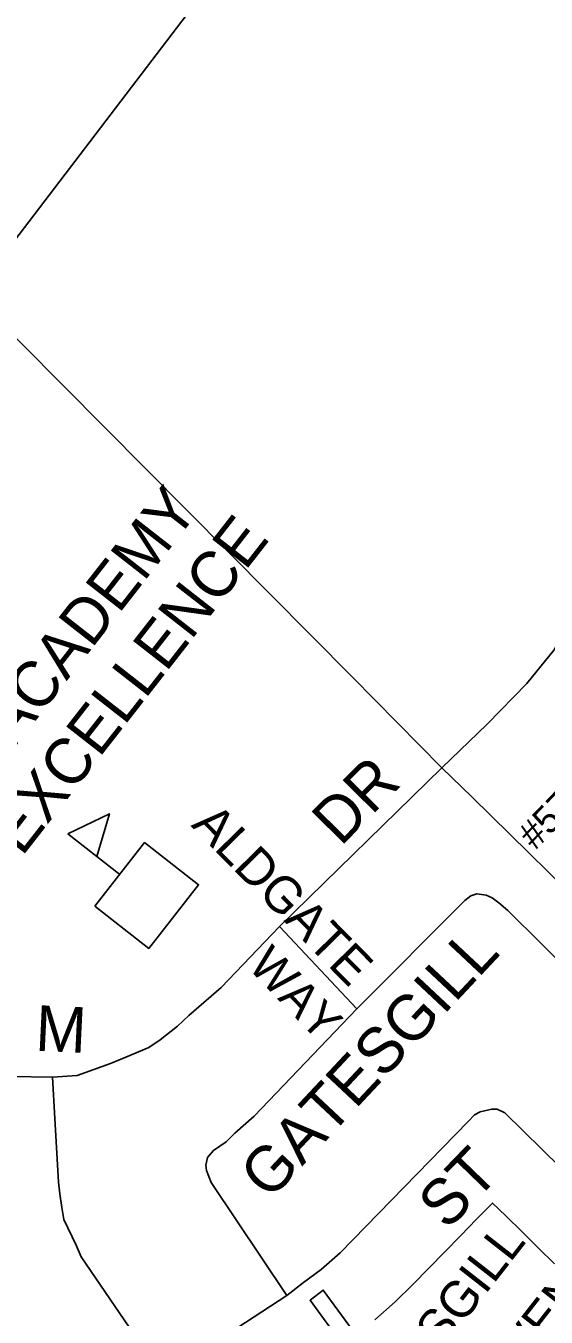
# Model space of a CAD drawing. Extents: x 586326 to 623965, y 4819854 to 4857850.
# Drawn here: x 597777 to 598062, y 4839351 to 4840059 of the extents above; entities that cross this region are included whole.
import ezdxf

# ---------------------------------------------------------------- set-up
doc = ezdxf.new("R2010")
doc.units = 0
for name, color, linetype in [('Cemeteries', 7, 'Continuous'), ('Major Rds and Hwys', 7, 'Continuous'), ('Minor Rd Lbls', 7, 'Continuous'), ('Minor Rds', 7, 'Continuous'), ('Park Lbls', 7, 'Continuous'), ('Park Outlines', 7, 'Continuous'), ('Private Rd Lbls', 7, 'Continuous'), ('Proposed Secondary Rds', 7, 'Continuous'), ('School Syms_Lbls', 7, 'Continuous'), ('Secondary Rds Lbls', 7, 'Continuous')]:
    doc.layers.add(name, color=color, linetype=linetype)

msp = doc.modelspace()

# ---------------------------------------------------------------- linework, layer by layer
at = {"layer": 'Major Rds and Hwys'}
for points in [[(597747.55, 4839911.46), (597898.45, 4840109.35), (597999.82, 4840250.81)], [(598004.81, 4839652.2), (597955.66, 4839701.74), (597751.53, 4839907.45), (597747.55, 4839911.46)], [(598294.8, 4839367.57), (598241.06, 4839420.31), (598021.17, 4839636.15), (598004.81, 4839652.2)]]:
    msp.add_lwpolyline(points, dxfattribs=at)
at = {"layer": 'Minor Rds'}
for points in [[(598077.81, 4839537.46), (598040.92, 4839573.89), (598035.95, 4839578.09), (598032.36, 4839580.81), (598029.11, 4839582.32), (598023.91, 4839582.98), (598020.64, 4839582.04), (598017.31, 4839579.41), (597958.19, 4839519.93)], [(597915.67, 4839565.21), (597958.19, 4839519.93)], [(597958.19, 4839519.93), (597901.89, 4839461.27), (597891.26, 4839451.82), (597886.54, 4839447.1), (597879.45, 4839442.37), (597876.18, 4839438.56), (597875.41, 4839434.33), (597875.68, 4839431.42), (597878.17, 4839424.87), (597919.78, 4839362.93)], [(597851.74, 4839318.45), (597806.99, 4839384.12), (597804.3, 4839390.42), (597797.5, 4839404.46), (597796.33, 4839411.08), (597795.19, 4839418.56), (597794.53, 4839425.02), (597792.61, 4839459.92), (597791.26, 4839482.53)], [(597919.78, 4839362.93), (597928.95, 4839369.98), (597938.56, 4839377.08), (597948.94, 4839386.32), (598019.13, 4839458.3), (598022.61, 4839461.93), (598025.75, 4839463.52), (598032.06, 4839465.09), (598035.1, 4839464.93), (598039.31, 4839463), (598069.83, 4839433.04)], [(597851.74, 4839318.45), (597919.78, 4839362.93)]]:
    msp.add_lwpolyline(points, dxfattribs=at)
at = {"layer": 'Park Outlines'}
for points in [[(598066.55, 4839380.23), (598057.63, 4839388.98), (598048.71, 4839397.73), (598039.79, 4839406.48), (598032.57, 4839413.55), (598023.82, 4839404.63), (598015.07, 4839395.72), (598006.31, 4839386.8), (597997.56, 4839377.88), (597988.81, 4839368.96), (597979.09, 4839359.45), (597967.93, 4839349.54)], [(597957.7, 4839341.17), (597939.7, 4839365.8), (597932.45, 4839360.28), (597950.64, 4839335.39)]]:
    msp.add_lwpolyline(points, dxfattribs=at)
at = {"layer": 'Proposed Secondary Rds'}
for points in [[(598004.81, 4839652.2), (598029.54, 4839676.08), (598051.33, 4839698.29), (598066.41, 4839716.73), (598071.44, 4839726.37), (598076.89, 4839736.84), (598080.66, 4839748.57), (598083.17, 4839757.79), (598089.88, 4839790.06)], [(598004.81, 4839652.2), (597915.67, 4839565.21)], [(597915.67, 4839565.21), (597883.78, 4839531.74), (597866.06, 4839516.39), (597859.77, 4839510.48), (597850.33, 4839502.94), (597844.01, 4839498.91), (597831.54, 4839493.5), (597823.07, 4839489.97), (597804.71, 4839483.53), (597791.26, 4839482.53)], [(597791.26, 4839482.53), (597768.03, 4839482.92), (597751.11, 4839485.29), (597736.14, 4839488.44), (597712.92, 4839499.07)]]:
    msp.add_lwpolyline(points, dxfattribs=at)
at = {"layer": 'School Syms_Lbls'}
msp.add_line((597828.09, 4839593.74), (597799.68, 4839615.93), dxfattribs=at)
for points in [[(597799.68, 4839615.93), (597822.45, 4839626.96), (597815.54, 4839603.46)], [(597814.45, 4839576.29), (597841.72, 4839611.18), (597871.33, 4839588.05), (597844.06, 4839553.16)]]:
    msp.add_lwpolyline(points, close=True, dxfattribs=at)

# ---------------------------------------------------------------- texts
at = {"layer": 'Cemeteries'}
for s, p in [('(PEEL CO. MANOR)', (598046.65, 4839274.35)), ('EVENTIDE', (598040.71, 4839309.08))]:
    msp.add_text(s, height=20, rotation=52.00002, dxfattribs=at).set_placement(p)
at = {"layer": 'Minor Rd Lbls'}
for s, height, rotation, p in [('ALDGATE', 19.998, 314.43557, (597866.82, 4839620.35)), ('GATESGILL', 25.002, 46.87693, (597910.3, 4839414.51)), ('WAY', 18.998, 313.6678, (597897.74, 4839542.97)), ('ST', 25.002, 45.97104, (598007.64, 4839398.1))]:
    msp.add_text(s, height=height, rotation=rotation, dxfattribs=at).set_placement(p)
at = {"layer": 'Park Lbls'}
msp.add_text('GATESGILL', height=19.992, rotation=52.00002, dxfattribs=at).set_placement((597959.85, 4839275.18))
at = {"layer": 'Private Rd Lbls'}
msp.add_text('#57 BRICKYARD ', height=15, rotation=45.79285, dxfattribs=at).set_placement((598055.94, 4839606.62))
at = {"layer": 'School Syms_Lbls'}
for s, p in [('XYNA ACADEMY', (597708.57, 4839583.87)), ('OF EXCELLENCE', (597740.19, 4839559.16))]:
    msp.add_text(s, height=25, rotation=52.00002, dxfattribs=at).set_placement(p)
at = {"layer": 'Secondary Rds Lbls'}
for s, height, rotation, p in [('DR', 25.002, 45.35152, (597949.24, 4839608.63)), ('M', 25, 357.27371, (597781.48, 4839497.1))]:
    msp.add_text(s, height=height, rotation=rotation, dxfattribs=at).set_placement(p)

doc.saveas('drawing.dxf')
